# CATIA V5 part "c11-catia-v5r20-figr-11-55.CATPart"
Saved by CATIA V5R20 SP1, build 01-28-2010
Part number: Part1
Bounding box of the stored display mesh (mm): x -59.829 to 59.829, y -71.429 to 72.174, z -61 to 76
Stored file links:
  D:\v5_r20\psrt_files_downloaded\c11\c11-catia-v5r20-figr-11-55.CATPart
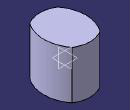
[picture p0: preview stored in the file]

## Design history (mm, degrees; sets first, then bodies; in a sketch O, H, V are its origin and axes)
Set1
  Extrude1: Element1 Sketch1, Lim1 76, Lim2 61, Direction xy-plane
Body1 (main body)
  Sketch1 on xy-plane, origin (0, 0, 0), H (0, 1, 0), V (-1, 0, 0)
    arc A1 centre (0, -40) radius 100 from (-60, 40) to (60, 40) cw
    point P2 (0, 60)
    point P3 (-60, 40)
    point P4 (60, 40)
    axis line L1 (-90, 0) -> (80, 0)
    point P6 (80, 0)
    point P7 (60, -40)
    point P8 (-60, -40)
    arc A2 centre (0, 40) radius 100 from (-60, -40) to (60, -40) ccw
    arc A3 centre (4.2857, 0) radius 75.7143 from (-60, 40) to (-60, -40) ccw
    arc A4 centre (0.3727, 0) radius 71.8012 from (60, -40) to (60, 40) ccw
    coincidence: A1 P2, P2 V, A3 P6
    horizontal: L1 H
    symmetry: P4 P7 L1, P3 P8 L1, A1 A2 L1
    tangency: A4 A3
  Sketch2 on xy-plane, origin (0, 0, 0), H (1, 0, 0), V (0, 1, 0)
    spline S1 through (80, 90) (60, 60) (70, 0) (50, -50) (50, -80)
    point P1 (70, 0)
    coincidence: P1 H
  CloseSurface1: CloseElement Extrude1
